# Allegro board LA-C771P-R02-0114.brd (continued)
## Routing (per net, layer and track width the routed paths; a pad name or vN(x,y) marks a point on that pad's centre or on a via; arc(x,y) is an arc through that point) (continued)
VCOUT0_MAIN_PWR_ON: length 174.8
  TOP w0.203: UB1.104 78.03,16.57 78.02,16.57
  TOP w0.254: v3(75.8,18.55) 75.8,18.35 77.58,16.57 78.02,16.57 ; v3(103.84,19.97) 103.84,13.04 v3(104.6,12.28)
  IN2 w0.254: v3(104.6,12.28) 105.11,11.77 109.16,11.77 109.87,11.06 124.15,11.06 128.31,6.89 179.33,6.89 203.43,31 203.43,41.97 202.11,43.29 196.04,43.29 195.77,43.56 v3(195.14,43.56) ; v3(75.8,18.55) 75.98,18.72 77.08,18.72 78.35,20 85.69,20 86,20.3 86.78,20.3 88.43,21.95 90.05,21.95 90.1,21.91 90.1,21.9 90.38,21.61 90.39,21.61 90.74,21.26 97.77,21.26 99.05,19.98 103.83,19.98 v3(103.84,19.97)
  BOTTOM w0.254: PR307.1 v3(195.14,43.56)
VCOUT1_PROCHOT#: length 197.1
  TOP w0.203: v3(119.21,8.37) 119.21,18.32 117.79,19.74 v3(117.79,19.73) ; v3(86.57,18.8) 86.57,18.47 84.94,16.84 84.94,16.54 84.79,16.39 84.05,16.39 PR111.1 ; RB24.1 82.46,16.08 81.92,16.62 v2(81.47,16.62) 81.21,16.62 80.76,16.17 UB1.103
  TOP w0.254: RB24.1 82.91,15.75 83.42,15.75 PR111.1
  IN2 w0.203: v3(207.58,68.06) 207.58,67.66 209.43,65.8 209.43,31 182.56,4.12 127.41,4.12 123.17,8.37 v3(119.21,8.37) ; v3(86.57,18.8) 86.93,18.8 87.93,19.81 95.32,19.81 95.76,19.37 103.14,19.37 103.29,19.22 107.03,19.22 107.27,19.22 107.79,19.74 117.79,19.74 v3(117.79,19.73)
  BOTTOM w0.203: v3(207.58,68.06) 206.03,69.6 PR224.1
VGA_CLKREQ#: length 9.1
  TOP w0.102: RPC3.3 124.35,93.18 v2(122.79,91.63) 120.85,89.68 120.28,89.68 v3(119.74,89.14)
  BOTTOM w0.102: UC4.BG3 120.25,89.14 v3(119.74,89.14)
VGA_V1P35_S3_F1:
  vias: v2(123.55,93.48)
VGATE: length 163.8
  TOP w0.203: v3(70.11,29.89) 70.13,29.87 UB1.21
  TOP w0.254: v3(102.93,31.15) 102.87,31.09 102.87,18.96 v3(102.95,18.88)
  IN2 w0.203: v3(102.95,18.88) 102.96,18.87 107.86,18.87 108.22,19.24 154.13,19.24 164,29.1 164,49.32 161.59,51.72 161.59,56.08 157.92,59.75 153.55,59.75 152.64,58.84 151.52,58.84 150.91,59.44 150.91,62.96 151.02,63.07 152.1,63.07 v3(152.14,63.1)
  IN2 w0.254: v3(102.93,31.15) 102.01,30.23 99.85,30.23 98.78,31.3 91.93,31.3 90.4,29.77 88.57,29.77 87.34,28.55 76.27,28.55 75.55,27.82 72.18,27.82 v3(70.11,29.89)
  BOTTOM w0.254: PU602.15 153.81,63.07 152.16,63.07 v3(152.14,63.1) 151.78,63.46 PR729.1
VGFX_VSNS: length 97.6
  TOP w0.254: v3(119.43,91.97) 118.79,91.33 118.22,91.33 v1(117.2,90.32) 116.9,90.01 116.9,86.54 117.22,86.22 v3(117.44,86.22) 117.63,86.03 117.63,84.26 118.07,83.82 118.73,83.82 119.08,83.47 119.08,82.01 119.43,81.67 RC71.2
  IN1 w0.254: v3(164.24,56.65) 166.59,59 166.59,78.61 165.5,79.7 165.5,80.73 161.24,85 152.72,85 152.18,85.54 150.16,85.54 149.35,84.73 147.56,84.73 146.74,85.54 133.88,85.54 129.7,89.72 129.17,89.72 126.71,92.18 119.64,92.18 v3(119.43,91.97)
  BOTTOM w0.254: UC4.BB8 117.61,86.22 v3(117.44,86.22) ; v3(164.24,56.65) 164.24,58.17 163.63,58.78 162.26,58.78 PC705.1 162,59.01 PR703.2 161.14,59.01 161.13,59 PR701.2
VL: length 76.3
  TOP w0.508: 22.51,7.58 R13.2 ; 22.51,7.58 22.99,8.06 31.96,8.06 v3(32.88,7.14) ; 22.51,7.58 22.16,7.93 16.7,7.93 R6.2
  IN1 w0.508: v3(45.27,51.16) 44.46,50.35 40.63,50.35 38.82,48.54 38.82,46.85 35.97,44 35.97,33.46 38.16,31.28 38.16,27.96 40.7,25.42 v3(40.7,14.54)
  IN2 w0.508: v3(32.88,7.14) 34.12,7.14 40.7,13.72 v3(40.7,14.54)
VMB:
  vias: v2(208.77,84.72)
VMB2:
  vias: v2(205.7,92.01) v2(207.54,92.62) v2(207.57,90.51)
VR_HOT#: length 123.6
  TOP w0.102: v3(85.99,18.78) v2(85.18,17.97) 84.43,17.22 RB26.1
  TOP w0.203: PR724.1 154.11,58.18 154.77,58.83 v3(154.92,58.83)
  IN2 w0.127: v3(154.92,58.83) 155.08,58.83 155.7,59.44 157.78,59.44 161.3,55.92 161.3,51.13 163.46,48.98 163.46,29.59 154.01,20.15 107.78,20.15 107.15,19.52 103.41,19.52 103.26,19.66 96.15,19.66 95.71,20.1 87.74,20.1 87.11,19.47 86.49,19.47 85.99,18.96 v3(85.99,18.78)
  BOTTOM w0.203: PU602.6 155.25,59.16 v3(154.92,58.83) 155,58.75 PC744.1
VR_ON: length 147.1
  TOP w0.203: UB1.108 78.6,18.17 78.18,18.59
  TOP w0.254: 78.18,18.59 76.91,19.86 v3(76.49,19.86)
  BOTTOM w0.203: v3(76.49,19.86) 77.62,19.86 v2(78.11,20.35) 78.89,21.14 84.24,21.14 85.15,20.23 88.6,20.23 88.86,19.97 102.09,19.97 102.57,19.49 113.34,19.49 116.13,16.7 120.88,16.7 127.87,9.71 161.66,9.71 166.15,14.2 166.15,44.01 158.08,52.08 PR717.1
VR_SVID_ALERT#: length 95.8
  TOP w0.102: v3(156.26,58.78) 156.26,58.82 156.81,59.37 v2(156.85,59.37)
  IN2 w0.127: v3(90.2,79.26) 90.2,79.99 91.37,81.16 95.69,81.16 96.07,80.78 97.49,80.78 100.11,78.16 100.29,78.16 100.49,77.96 104.93,77.96 105.26,77.63 105.26,76.18 105.57,75.87 105.57,75.21 105.29,74.94 105.29,74.55 105.47,74.38 105.95,74.38 106.64,73.69 106.64,72.84 106.98,72.5 108.17,72.5 108.3,72.36 108.3,72.36 109.37,71.3 112.44,71.3 113.28,70.45 116.33,70.45 118.34,68.43 118.34,67.67 119.49,66.53 119.82,66.53 121.01,65.33 121.01,64.42 121.66,63.77 121.66,62.7 134.75,49.62 153.17,49.62 155.53,51.97 155.53,57.66 156.26,58.4 v3(156.26,58.78)
  BOTTOM w0.102: RC39.2 89.74,78.57 RC40.2 89.8,78.62 90.2,79.03 v3(90.2,79.26) ; v3(156.26,58.78) 156.26,58.82 156.05,59.03 PU602.4
VR_SVID_ALERT#_SOC: length 10
  TOP w0.102: v3(95.68,78.92) v2(95.68,78.27)
  IN2 w0.102: 95.15,79.33 95.28,79.33 v3(95.68,78.92)
  IN2 w0.127: v3(90.91,79.56) 90.91,79.13 91.14,78.9 92.93,78.9 93.36,79.33 95.15,79.33
  BOTTOM w0.102: UC4.B24 98.22,78.91 97.58,78.91 97.42,78.75 95.86,78.75 v3(95.68,78.92) ; v3(90.91,79.56) 90.91,78.83 RC40.1
VR_SVID_CLK: length 99.4
  TOP w0.102: PR726.1 157.35,56.66 v3(157.35,56.54)
  IN2 w0.127: v3(157.35,56.54) 157.35,52.14 153.66,48.45 134.26,48.45 119.65,63.06 119.65,64.44 118.7,65.4 118.09,65.4 117.43,66.06 117.43,66.63 114.84,69.22 113.54,69.22 112.27,70.49 109.53,70.49 108.06,71.96 106.86,71.96 106.18,72.65 106.18,73.49 105.8,73.87 104.81,73.87 104.35,74.32 104.35,76.76 103.77,77.35 101.2,77.35 100.79,76.94 99.83,76.94 99.4,77.37 99.4,77.86 97.42,79.84 93.15,79.84 92.72,79.41 91.59,79.41 91.52,79.47 v3(91.52,79.51)
  BOTTOM w0.102: PR726.1 157.35,56.66 v3(157.35,56.54) ; v3(91.52,79.51) 91.52,78.13 v1(91.89,77.76) 91.95,77.69 95.3,77.69 95.64,78.03 97.9,78.03 98.15,78.29 98.44,78.29 UC4.C25
VR_SVID_CLK_R: length 5.4
  TOP w0.102: v2(159.52,57.13) 158.73,57.13 v3(157.08,58.78)
  BOTTOM w0.102: PR720.2 157.08,58.44 v3(157.08,58.78) 156.45,59.41 PU602.3
VR_SVID_DATA: length 89.8
  TOP w0.102: PR725.1 156.11,57 v3(156.11,56.5)
  IN2 w0.127: v3(156.11,56.5) 156.11,51.73 153.41,49.03 134.5,49.03 120.24,63.3 120.24,64.69 118.94,65.98 118.36,65.98 118.02,66.33 118.02,66.88 117,67.89 117,68.86 115.96,69.91 113.35,69.91 112.33,70.92 109.42,70.92 108.08,72.27 106.88,72.27 106.41,72.74 106.41,73.59 105.85,74.15 105.29,74.15 104.98,74.45 104.98,74.96 105.29,75.27 105.29,75.7 104.91,76.08 104.91,76.69 103.94,77.65 100.39,77.65 100.18,77.86 99.88,77.86 97.31,80.42 92.56,80.42 v3(92.13,79.99)
  BOTTOM w0.102: v3(156.11,56.5) 156.11,57 PR725.1 ; v3(92.13,79.99) 92.36,79.76 RC41.2
VR_SVID_DATA_R: length 3.5
  TOP w0.102: v2(154.74,59.88) 155.65,58.97 v3(155.65,58.76)
  BOTTOM w0.102: PU602.5 v3(155.65,58.76) 155.89,58.52 PR721.2
VR_SVID_DATA_SOC: length 5
  BOTTOM w0.102: UC4.A25 97.7,78.29 95.3,78.29 95.07,78.06 v2(94.69,78.06) 93.91,78.06 RC41.1
VSUM+: length 8.1
  TOP w0.203: PC758.1 PC759.1 PR739.1 151.45,60.41 151.39,60.35 PR735.2 ; PR735.2 151.39,59.09 151.46,59.02 PR734.1 v2(151.46,57.77) ; PR735.2 v3(152.28,59.72)
  BOTTOM w0.203: v3(152.28,59.72) 152.28,59.72 152.65,60.08 152.88,60.08 153.12,60.31 153.12,60.82 153.36,61.07 PU602.10
VSUM-: length 22.8
  TOP w0.203: PC761.2 150.12,63.44 150.13,63.46 PR738.2 PC758.2 PC759.2 ; PR739.2 v2(148.32,60.79) 146.92,60.79 v3(146.85,60.87)
  TOP w0.254: PR739.2 PC759.2
  IN2 w0.203: v3(149.56,67.06) 148.37,67.06 147,65.69 147,61.02 v3(146.85,60.87)
  BOTTOM w0.203: v3(149.56,67.06) 149.97,67.47 PH701.2 149.97,71.58 149.29,72.26 PL703.3
VSUMG+: length 7.2
  TOP w0.254: v3(159.16,59.47) 159.55,59.47 159.81,59.73 PR714.2 ; PC727.2 PC726.2 PR711.2 160.23,60.31 160.28,60.25 PR714.2 ; PR714.2 160.28,59.14 160.22,59.07 PR710.2
  BOTTOM w0.254: v3(159.16,59.47) 158.96,59.47 158.58,59.85 158.58,60.36 158.27,60.67 PU602.32
VSUMG-: length 52.8
  TOP w0.254: PR704.2 162,63.46 PR706.1 PC727.1 PC726.1 PR711.1 164.27,60.79 v3(164.37,60.69)
  IN2 w0.203: v3(164.37,60.69) 166.31,62.63 166.31,78.53 165.27,79.57 165.27,81.78 162.22,84.83 153.03,84.83 152.45,85.42 151.15,85.42 v3(150.67,84.93)
  BOTTOM w0.203: v3(150.67,84.93) 150.08,84.93 PH702.1 149.82,80.96 149.34,80.47 PL702.3
VTTREF_DDR: length 5.1
  BOTTOM w0.102: 154.24,35.88 153.98,36.15 153.98,37.09 v2(154.34,37.45)
  BOTTOM w0.203: PC415.1 154.12,34.87 154.12,34.04 154.07,34 PU303.4
  BOTTOM w0.254: PC415.1 154.24,35.88
WAKE#_R: length 5.7
  BOTTOM w0.102: v1(177.03,89.34) RM2.2 174.37,89.34 RM3.2 174.33,89.62 172.95,91 JWLAN1.1
WL_RST#: length 4.4
  TOP w0.102: JWLAN1.22 161.35,93 162.34,92.01 RM6.1 v1(161.25,91.32)
WLAN_BT_OFF#: length 32.7
  TOP w0.102: v3(150.59,90.05) 150.08,89.54 149.64,89.54 v1(149.36,89.83) 149.36,89.83 148.83,90.36 148.83,91.27 RM21.1
  IN1 w0.127: v3(172.17,87.13) 171.95,87.13 170.43,88.65 169.13,88.65 168.64,89.15 166.85,89.15 166.05,89.95 161.74,89.95 161.45,89.66 156.57,89.66 156.03,90.2 154.34,90.2 153.76,89.63 150.82,89.63 150.59,89.86 v3(150.59,90.05)
  BOTTOM w0.102: v3(172.17,87.13) 172.23,87.19 QM1.3 172.23,88.29 RM18.1 171.1,89.42 171.1,90.46 171.35,90.71 JWLAN1.5
WLAN_CLKREQ#: length 75.5
  TOP w0.102: v3(118.52,89.18) 119.56,90.23 120.71,90.23 123.85,93.37 v1(123.85,93.9) RPC3.2
  IN1 w0.127: v3(169.83,87.72) 169.06,86.94 167.62,86.94 165.63,88.93 162.17,88.93 161.88,88.64 156.69,88.64 156.27,88.22 154.22,88.22 153.82,88.62 149.42,88.62 138.17,99.87 126.63,99.87 125.13,98.37 123.69,98.37 v3(122.85,97.53)
  IN2 w0.102: v3(118.52,89.18) 118.52,90.1 118.88,90.46 118.88,90.48 119.15,90.75
  IN2 w0.127: 119.15,90.75 119.82,91.42 120.22,91.42 123.06,94.26 123.06,94.83 122.85,95.03 v3(122.85,97.53)
  BOTTOM w0.102: RM4.1 169.82,87.78 169.82,87.73 v3(169.83,87.72) ; UC4.BE3 118.61,89.09 v3(118.52,89.18)
WLAN_CLKREQ#_R: length 3.6
  BOTTOM w0.102: RM4.2 v1(170.11,89.37) 170.55,89.81 JWLAN1.7
XDP_H_PRDY#: length 13
  BOTTOM w0.102: UC4.D18 99.51,81.93 99.04,82.4 98.75,82.56 98.63,82.67 98.63,82.82 98.2,83.24 98.2,83.37 97.49,84.08 96.65,84.08 96.27,84.46 95.15,84.46 v1(93.81,85.81) 93.64,85.98 89.07,85.98 RC38.2
XDP_H_PREQ_BUF#: length 4.3
  TOP w0.102: v2(96.8,82.17) 97.78,82.17 RC45.2 98.54,81.62 98.84,81.92 99.6,81.92 v3(99.93,82.25)
  BOTTOM w0.102: UC4.F16 100.19,82.51 v3(99.93,82.25)
XDP_H_TCK: length 14.4
  TOP w0.102: RPC6.7 88.81,83.33 90.07,84.59 91.88,84.59 v2(92.24,84.95) 92.38,85.09 v3(93.53,85.09)
  IN2 w0.102: 95.15,84.87 95.68,84.87 96.34,84.21 97.75,84.21 98.05,83.91 99.32,83.91 v3(99.68,84.27)
  IN2 w0.127: 95.15,84.87 94.59,84.87 94.33,85.13 93.57,85.13 v3(93.53,85.09)
  BOTTOM w0.102: UC4.D14 99.51,84.1 v3(99.68,84.27)
XDP_H_TDI: length 15.6
  TOP w0.102: RPC6.5 v2(88.65,82.33) 89.33,82.32 90.33,83.32 v3(90.71,83.32)
  IN2 w0.102: 95.15,84.26 95.72,84.26 96.96,83.02 99.61,83.02 v3(99.81,83.21)
  IN2 w0.127: v3(90.71,83.32) 91.1,83.71 93.13,83.71 93.68,84.26 95.15,84.26
  BOTTOM w0.102: UC4.F12 100.07,84.65 100.07,84.12 99.88,83.92 99.88,83.28 v3(99.81,83.21)
XDP_H_TDO: length 1.9
  TOP w0.102: RC46.2 100.79,82.22 v3(100.71,82.3)
  BOTTOM w0.102: v3(100.71,82.3) 100.9,82.49 UC4.G16
XDP_H_TMS: length 15.3
  TOP w0.102: RPC6.6 89,82.83 89.97,83.8 v2(90.38,83.8) 90.83,83.8 v3(91.35,83.28)
  IN2 w0.102: v3(100.41,83.26) 99.95,82.81 96.88,82.81 95.73,83.96 95.29,83.96
  IN2 w0.127: 95.29,83.96 93.74,83.96 93.06,83.28 v3(91.35,83.28)
  BOTTOM w0.102: v3(100.41,83.26) 100.19,83.48 UC4.F14
XDP_H_TRST#: length 16.4
  TOP w0.102: RPC6.8 88.5,83.83 89.57,84.9 91.32,84.9 91.96,85.53 94.06,85.53 94.24,85.35 v2(94.24,85.2) 94.24,84.94 v3(93.99,84.69)
  IN2 w0.102: 95.15,84.57 95.7,84.57 96.3,83.96 97.67,83.96 97.92,83.71 100.06,83.71 v3(100.52,84.18)
  IN2 w0.127: v3(93.99,84.69) 94.11,84.57 95.15,84.57
  BOTTOM w0.102: v3(100.52,84.18) 100.9,84.55 UC4.G12
XDP_OBSDATA_A0: length 2.5
  TOP w0.102: T10.1 101.88,80.07 v3(102.53,79.42)
  BOTTOM w0.102: UC4.N24 103.22,79.42 v3(102.53,79.42)
XDP_OBSDATA_A1: length 2.1
  TOP w0.102: T11.1 102.42,80.68 v3(102.11,80.37)
  BOTTOM w0.102: v3(102.11,80.37) 102.54,80.37 UC4.M20
XDP_OBSDATA_A2: length 1.7
  TOP w0.102: T12.1 101.34,81.94 v3(101.34,82.3)
  BOTTOM w0.102: v3(101.34,82.3) 101.61,82.04 UC4.J18
XDP_OBSDATA_A3: length 1.2
  TOP w0.102: v3(102.6,82.22) 102.6,82.35 T13.1
  BOTTOM w0.102: v3(102.6,82.22) 103.01,81.81 UC4.M18
XDP_RSTBTN#: length 5.9
  BOTTOM w0.102: UC4.BG9 120.92,86.15 121.32,86.55 122.34,86.55 122.88,87.09 122.88,87.55 123.33,88 T7.1 124.75,88.12 CC15.1
XTAL_25M_IN: length 13.5
  IN2 w0.127: v3(112.5,90.86) 112.2,90.56 112.2,86.12 111.5,85.41 v3(110.57,85.41)
  BOTTOM w0.102: UC4.AH12 110.75,85.41 v3(110.57,85.41) ; v3(112.5,90.86) 112.5,91.09 112.02,91.58 112.02,92.97 RC24.1 111.94,93.07 111.28,93.73 111.03,93.73 110.59,94.17 CC12.1 110.59,95.24 YC1.1
XTAL_25M_OUT: length 14.9
  IN2 w0.127: v3(110.61,86.01) 111.56,86.01 111.97,86.42 111.97,90.87 111.36,91.48 v3(111.36,92.34)
  BOTTOM w0.102: v3(111.36,92.34) 111.03,92.67 RC24.2 110.6,93.05 109.53,94.12 CC13.1 109.85,94.73 109.85,96.44 YC1.3 ; UC4.AH10 110.84,85.78 v3(110.61,86.01)
XTLI: length 8.4
  BOTTOM w0.102: YL1.3 36.81,60.06 36.81,62.16 36.35,62.62 36.35,63.5 35.57,64.29 CL16.2 35.57,65.77 35.47,65.87 UL1.29
XTLO: length 6.1
  BOTTOM w0.102: UL1.28 35.87,65.95 35.87,65.95 35.87,65.69 v2(36.14,65.42) 37.01,64.55 CL13.2 37.01,64.29 37.5,63.81 37.5,61.55 YL1.1
N10380:
  vias: v2(37.77,89.47)
N16597291: length 1.1
  BOTTOM w0.102: PR304.2 v2(185.83,40.51)
N16598283: length 1.2
  BOTTOM w0.102: PC318.1 v2(50.53,49.87)
N16598457: length 1.9
  BOTTOM w0.102: v2(191.58,43.85) PC302.2 191.58,42.87
  BOTTOM w0.254: PR302.1 191.58,42.87 191.58,42.87
N16598563: length 1
  BOTTOM w0.254: PR309.1 PC317.2
N16600766: length 2.7
  TOP w0.381: v2(154.62,28.94) 154.13,28.46 v3(154.13,28.43)
  TOP w0.508: v3(154.13,28.43) 154.13,28.07 PC408.2 155.46,27.71 PR405.2
N16601416: length 2.9
  TOP w0.508: v2(151.47,27.25) PC417.1 150.18,27.82 PR403.2
N16602606:
  vias: v2(64.82,59.25)
N16602704:
  vias: v2(65.67,62.39)
N16603012: length 1.7
  TOP w0.254: PU501.2 60.94,59.18 v3(60.7,58.95) 60.12,58.37 PR502.2
N16605295: length 1.7
  TOP w0.102: PC602.1 71.71,79.79 v2(72.25,79.79)
N16605323: length 4.8
  TOP w0.102: v2(63.68,73) 63.68,72.77 64.3,72.15 64.6,72.15 PR603.2
  TOP w0.254: PU601.2 PR605.1 PC604.2 PR603.2
N16605357: length 2.3
  TOP w0.254: PU601.7 66.38,79.5 66.79,79.9 67.15,79.9 67.46,80.21 PR602.2
N16605441: length 5.6
  TOP w0.254: PR604.1 PC603.1 PR601.2 64.79,80.51 63.9,80.51 63.65,80.26 v2(63.65,79.97) 63.65,79.78 63.83,79.6 64.8,79.6 65.11,79.29 PU601.8
N16615810: length 3.3
  BOTTOM w0.203: PU602.8 154.45,59.97 153.83,59.34 152.92,59.34 v2(152.66,59.09) 152.33,58.76 PR722.2
N16616404: length 1.2
  BOTTOM w0.102: PR709.1 v2(162.52,64.53)
N16616872: length 1.4
  BOTTOM w0.102: PR730.1 151.25,66.72 v2(151.57,67.04)
N16617014: length 2.2
  TOP w0.102: v2(163.3,64.35) 163.3,64.36 PR704.1
  TOP w0.203: PR704.1 162,64.35 PC716.1
N16617018: length 5.1
  TOP w0.254: PC716.2 PR706.2 160,63.46 158.99,62.45 v2(158.99,61.78) 158.99,61.17 v3(158.78,60.96)
  BOTTOM w0.254: v3(158.78,60.96) 158.67,61.07 PU602.31
N16617032: length 1.9
  TOP w0.102: PC761.1 149.61,64.41 v2(149.61,65.31)
  TOP w0.203: PC761.1 149.67,64.35 PR737.2
N16617036: length 5.4
  TOP w0.203: PR737.1 PR738.1 151.68,63.69 152.52,63.69 152.83,63.37 v2(152.83,62.77) 152.83,61.52 v3(152.97,61.38)
  BOTTOM w0.203: PU602.11 153.05,61.47 v3(152.97,61.38)
N16617104: length 4.2
  BOTTOM w0.203: PC713.1 160.23,60.82 PR702.1 PR707.1 159.7,62.57 159.4,62.27 PU602.28
N16617138: length 3.1
  TOP w0.102: v3(157.83,58.77) 158.25,58.35 v2(158.25,58.33)
  BOTTOM w0.203: PR717.2 158.08,58.52 v3(157.83,58.77) 157.31,59.29 157.16,59.29 156.85,59.6 PU602.2
N16617166: length 6.4
  TOP w0.102: PR123.2 156.47,55.3 v1(157.06,54.72)
  TOP w0.203: PR123.2 155.86,55.76 155.33,56.3 PR122.2 155.02,56.5 PC750.1 PR724.2 155.87,58.12 PR725.2 PR726.2
N16617198: length 8.7
  BOTTOM w0.102: v2(163.38,59.62) 163.11,59.89 PR705.1
  BOTTOM w0.203: PC713.2 159.67,60.46 159.67,61.43 159.23,61.87 PU602.29 ; PC713.2 160.24,59.03 PR703.1 160.23,58.15 PC714.1 ; PC713.2 PC719.2 PR705.1
N16617206: length 4.2
  BOTTOM w0.203: PC757.2 151.44,61.67 PC760.2 151.45,61.68 151.45,62.56 PR732.2 152.38,62.57 v2(152.39,62.58) 152.48,62.67 PU602.14
N16617222: length 12.1
  BOTTOM w0.102: v2(146.59,62.29) 147.58,61.3 149.03,61.3 149.18,61.15 149.18,60.37 PR733.2
  BOTTOM w0.203: PC757.1 151.98,60.43 151.98,61.54 152.7,62.27 PU602.13 ; PC757.1 PR741.1 PR733.2 ; PC757.1 151.45,59.88 PR740.2 151.44,59 PR736.2
N16617226: length 0.9
  BOTTOM w0.203: PR702.2 161.14,61.29 161.13,61.27 PC719.1
N16617230: length 5
  BOTTOM w0.102: PC738.1 154.03,66.45 v2(153.33,67.14)
  BOTTOM w0.254: PC738.1 154.51,66.45 155.41,66.45 PR719.2 155.41,66.37 155.94,65.84 155.94,65.28 156.05,65.17 PU602.21
N16617308: length 2.7
  BOTTOM w0.254: PU602.27 159.18,62.67 159.97,63.46 PR712.2
N16617390: length 0.9
  BOTTOM w0.203: PC760.1 150.55,61.67 PR741.2
N16617462: length 3.4
  BOTTOM w0.102: v2(148.5,57.75) 149.36,56.89 150.22,56.89 PC756.2
  BOTTOM w0.254: PR736.1 151.43,57.23 150.55,57.23 PC756.2
N16617530: length 47.4
  TOP w0.203: v3(163.1,58.02) 162.44,58.68 PR710.1
  IN2 w0.203: v3(148.91,85.35) 149.03,85.48 150.73,85.48 151.05,85.8 152.58,85.8 153.21,85.16 162.35,85.16 165.73,81.79 165.73,79.85 166.85,78.74 166.85,61.77 v3(163.1,58.02)
  BOTTOM w0.203: PH702.2 v3(148.91,85.35)
N16617586: length 2.4
  BOTTOM w0.102: 149.66,61.67 149.19,62.14 v2(148.37,62.14)
  BOTTOM w0.203: 149.66,61.67 PC752.2 PR733.1
N16617598: length 2.1
  BOTTOM w0.102: PR701.1 161.68,56.67 v2(161.68,56.19)
  BOTTOM w0.203: PC714.2 PR701.1
N16617710: length 3.3
  BOTTOM w0.254: PR718.1 156.31,66.45 ; 156.31,66.45 157.19,66.45 PC733.2 ; 156.31,66.45 156.31,66.18 156.45,66.03 v2(156.45,65.41) PU602.22
N16617722: length 13.7
  TOP w0.203: PR734.2 149.96,58.67 v2(149.58,58.3) 148.66,58.3 v3(146.87,60.08)
  IN2 w0.203: v3(149.03,66.56) 148.85,66.73 148.51,66.73 147.33,65.56 147.33,60.54 v3(146.87,60.08)
  BOTTOM w0.203: PH701.1 149.05,66.58 v3(149.03,66.56)
N16617766: length 1.8
  BOTTOM w0.102: PC724.1 v2(163,61.67)
  BOTTOM w0.254: PR705.2 PC724.1
N16618186: length 0.8
  TOP w0.102: 150.27,81.01 150.38,80.91 v2(151.01,80.91)
N16618510: length 45.6
  TOP w0.203: v3(162.8,59.32) 162.59,59.52 161.89,59.52 PR714.1
  IN2 w0.203: v3(162.8,59.32) 162.8,60.71 164.22,62.14 164.22,81.47 161.25,84.43 152.8,84.43 152.16,85.07 151.52,85.07 v3(151.29,84.84)
  BOTTOM w0.203: PL702.2 150.76,80.47 150.46,80.77 150.46,84.02 v3(151.29,84.84)
N16618534: length 17.1
  TOP w0.203: PR735.1 148.58,59.72 v3(148.55,59.75)
  IN2 w0.203: v3(148.55,59.75) 148.24,60.05 148.24,64.5 v3(150.48,66.73)
  BOTTOM w0.203: v3(150.48,66.73) 150.48,71.44 151.29,72.26 PL703.2
N17087503: length 2.5
  TOP w0.305: UR1.8 v2(44.2,14.23) 43.31,13.33 RR1.2
N17458820: length 5.6
  TOP w0.102: LED3.1 24.29,2.74 v2(24.29,3.54) 24.29,4.07 23.55,4.81 R12.2 23.56,5.44 R15.2
N17500377: length 1.9
  TOP w0.203: UQ1.12 v3(186.7,25) 185.55,25 CQ2.2
N17500401: length 2.1
  TOP w0.203: CQ6.2 185.7,26.15 v3(186.17,26.15) 186.53,25.8 UQ1.10
N17500568: length 2.3
  TOP w0.203: CQ10.2 55.28,68.18 v2(54.41,68.18) 53.98,68.18 53.68,67.88 UQ2.12
N17500584: length 2.2
  TOP w0.203: UQ2.10 54.12,67.08 v3(54.19,67.01) 55.18,67.01 CQ14.2
N18372963: length 2.6
  BOTTOM w0.229: UL1.31 34.67,66.14 34.37,65.85 v2(34.37,65.49)
  BOTTOM w0.254: v2(34.37,65.49) 34.37,64.3 RL6.2
N18373572: length 4.4
  BOTTOM w0.102: UL1.25 37.07,66.15 37.55,65.67 38.21,65.67 38.67,65.21 39.15,65.21 39.73,64.63 TPL1.1
N18373578: length 2.7
  BOTTOM w0.102: TPL2.1 37.37,65.06 36.27,66.16 UL1.27
N18442348: length 3.3
  TOP w0.203: UB1.118 81.11,22.17 v2(81.5,22.56)
  TOP w0.254: v2(81.5,22.56) 82.13,23.19 82.13,23.2 RB25.2
N18492193:
  vias: v2(118.25,56.88)
N18492196:
  vias: v2(115.13,56.84)
N18535411: length 1.7
  TOP w0.102: v2(19.46,71) 18.27,71 RL8.2
N18535413: length 4
  BOTTOM w0.508: v3(19.78,64.4) 19.12,63.74 TL1.11 ; v3(19.73,68.42) 18.85,67.55 TL1.14
  vias: v1(19.96,69)
N18977277: length 4.1
  BOTTOM w0.102: v2(50.68,81.67) 51.7,82.69 CX13.1 51.75,82.71 RX11.2 51.75,84.84 QX2.2
N19132918: length 3.8
  BOTTOM w0.102: UC5.4 54.47,78.85 54.29,79.02 54.29,79.74 54.02,80.01 v2(53.49,80.01) 53.49,78.83 RC8.1
N19342204: length 4
  BOTTOM w0.102: RC12.1 60.89,77.15 59.95,77.15 v2(59.57,77.53) 59.57,78.31 UC6.4
N19670814: length 5.9
  BOTTOM w0.102: PR109.1 PR105.1 PR107.1 199.99,91.15 199.08,91.15 v2(198.97,91.27) 198.85,91.38 JBATT1.5
N19670901: length 2.9
  BOTTOM w0.102: v1(148.94,15.11) PR116.1
  BOTTOM w0.508: PR116.1 147.79,16.52 PD100.3
N19732471: length 5.1
  TOP w0.102: v2(123.81,89.44) v3(123.81,88.68)
  BOTTOM w0.254: RC74.2 124.57,89.79 124.04,89.26 124.04,88.91 v3(123.81,88.68) 123.02,88.68 122.22,87.88 121.6,87.88 UC4.BJ6
N19773650: length 5.3
  TOP w0.102: RW7.1 93.25,18.17 RW4.2 93.22,17.14 RW3.2 93.21,17.02 RW6.1 92.29,15.23 92.29,15.23 v2(92.29,14.51)
N19773695: length 6.6
  TOP w0.102: UW2.6 96.74,15.59 96.45,15.3 96.45,14.84 96.15,14.54 94.42,14.54 v2(94.14,14.82) 94.14,15.25 94.52,15.63 RW9.1 93.24,16.13 RW6.2
N19773710: length 4.5
  TOP w0.102: UW2.5 96.61,16.24 95.69,17.15 RW8.2 RW9.2 95.43,15.4 v2(95.9,14.93)
N19796007: length 14.2
  BOTTOM w0.102: v2(29.5,61.51) 29.5,61.03 CL15.1
  BOTTOM w0.254: CL15.1 28.65,60.18 27.87,60.18 27.86,60.18 27.8,60.18 27.79,60.18 26.02,60.18 25.59,60.61 25.59,63.41 25.92,63.74 ; 25.92,63.74 TL1.6 ; 25.92,63.74 25.56,64.09 25.56,67.29 25.81,67.55 TL1.3
N19801797: length 5.3
  BOTTOM w0.102: US1.3 16.48,38.35 16.21,38.08 v2(15.93,38.08) 15.64,38.08 15.27,38.45 RS2.1
N19854769: length 5.5
  TOP w0.102: JWLAN1.20 162.15,93.16 162.59,92.72 163.48,92.72 RM5.1 v1(165.86,91.32)
N19857635: length 6.1
  TOP w0.102: v1(153.56,88.06) 152.09,89.53 151.72,89.53 151.25,90 v3(151.25,90.05) 151.06,90.24 RM11.2
  BOTTOM w0.102: v3(151.25,90.05) 151.25,90.03 150.55,90.73 JWLAN1.49
N19992411: length 5
  TOP w0.254: v3(129.22,48.82) 127.82,47.42 RD5.2
  BOTTOM w0.254: v3(129.22,48.82) 128.33,47.94 JDIMM1.197
N19992423: length 5
  TOP w0.508: RD6.2 129.63,45 130.16,44.48 v3(130.52,44.48)
  BOTTOM w0.356: v3(130.52,44.48) 130.16,44.48 129.53,45.11 JDIMM1.201
N20191994: length 3.8
  TOP w0.102: v3(149.98,90.04) 149.98,90.12 RM21.2 RM12.2
  BOTTOM w0.102: v3(149.98,90.04) 149.98,90.03 149.75,90.26 JWLAN1.51
N20264849: length 4.6
  TOP w0.254: RS11.1 190.28,61.07 190.74,61.53 v2(191.09,61.53) 191.68,61.53 193.14,60.07 US2.13
N20529644: length 6.4
  TOP w0.102: v1(186.05,56.19) 186.04,56.19 186.8,55.43 186.8,55.31 RS20.1 187.1,54.62 188.37,53.35 188.37,52.46 187.99,52.08 187.35,52.08 US3.3
N20531465: length 4.2
  BOTTOM w0.102: QM1.5 171.73,85.6 RM20.1 ; RM20.1 170.98,85.35 170.98,85.89 171.23,86.14 QM1.6 ; RM20.1 v2(171.23,84.11)
N20897061: length 3.9
  TOP w0.102: R7.1 20.83,5.47 20.61,5.24 v2(20.61,4.4) 20.61,4.17 20.84,3.95 21.37,3.95 21.65,3.67 LED2.2
N20897066: length 2.6
  TOP w0.102: R13.1 22.51,4.56 v2(22.71,4.36) 23.15,3.91 LED3.2
N20897117: length 2.4
  TOP w0.102: R14.1 30.4,5.46 v2(30.4,4.35) LED4.2
N20897124: length 3.3
  TOP w0.102: LED1.2 14.4,3.1 15.01,3.1 15.5,3.59 v2(15.5,4.12) 15.5,5.11 R6.1
N21018227: length 3.4
  TOP w0.102: JODD1.11 225.77,109.74 223.63,109.74 T22.1
N23009332: length 3.9
  TOP w0.102: UA1.47 28.26,26.28 28.48,26.5 28.48,27.64 v2(29.07,28.23) 29.32,28.48 RA12.2
N23009443: length 2
  TOP w0.102: RA11.2 28.15,33.5 CA10.1 v2(29.17,33.48)
N23009457: length 4.6
  BOTTOM w0.102: v2(21.24,31.53) 21.24,31.08 RA30.1 22.54,29.77 RA31.1 23.17,29.5 CA30.2 23.83,29.51 CA32.2
N23009590: length 2.9
  BOTTOM w0.102: RA30.2 20.1,30.36 19.9,30.16 v2(19.9,30.01) 19.9,29.73 20.15,29.47 CA31.1
N23009788: length 1.8
  TOP w0.203: UA1.28 23.77,20.95 23.63,20.81 23.63,20.15 CA20.1
N23009828: length 2.2
  TOP w0.203: UA1.19 20.88,24.28 v3(20.73,24.42)
  BOTTOM w0.254: v3(20.73,24.42) 20.15,24.42 CA21.1
N23009845: length 4.1
  TOP w0.203: CA15.2 29.55,20.61 29.03,20.61 28.23,21.42 v3(28.23,21.78) 28.38,21.93 28.38,22.14 28.24,22.28 UA1.37
N23009849: length 6.1
  TOP w0.102: v2(30.54,18.04) 30.54,18.7 CA15.1
  TOP w0.203: CA15.1 30.13,18.98 28.74,20.38 27.1,20.38 26.57,20.91 UA1.35
N24385312: length 3.3
  BOTTOM w0.203: PU1.10 203.67,71.38 v2(203.95,71.1) 204.24,70.81 PR224.2
N24385422: length 1.4
  BOTTOM w0.102: PR220.2 v2(194.72,69.38)
N24385504: length 12.9
  TOP w0.102: v2(43.44,85.76) 43.44,86.14 v3(43.67,86.37)
  IN1 w0.508: v3(43.67,86.37) 39.76,86.37 37.98,84.59 v3(37.85,84.59)
  BOTTOM w0.381: PR211.1 38.51,86.16 39.15,86.79 39.33,86.79 PQ200.3 40.11,88.58 PR201.2
  BOTTOM w0.508: v3(37.85,84.59) 37.98,84.72 PR211.1
N24385542:
  vias: v2(187.56,67.95) v3(184.95,68.46) v3(185.64,68.46) v3(186.34,68.46)
N24385544: length 2.7
  BOTTOM w0.203: PU1.21 199.18,67.69 PR225.1 PR222.1
N24385582: length 1.7
  BOTTOM w0.203: PR226.1 199.58,67.31 PU1.20
N24385584: length 2.6
  TOP w0.102: v2(200.72,68.21) 200.31,68.21 v3(200.06,67.95)
  BOTTOM w0.203: PR227.1 200.5,67.51 v3(200.06,67.95) 199.98,68.04 PU1.19
N24385612: length 1.8
  TOP w0.102: v2(197.75,73.64) 197.27,73.64 v3(196.91,73.28)
  TOP w0.508: PC211.2 196.06,73.28 v3(196.91,73.28)
N24385618: length 5
  TOP w0.102: v2(201.05,77.83) 201.05,77.47 v3(201.32,77.2)
  BOTTOM w0.102: v3(201.32,77.2) PR215.2
  BOTTOM w0.203: PR216.1 201.39,74.67 201.39,73.73 201.18,73.52 PU1.6
  BOTTOM w0.254: PR216.1 PC212.1 PR215.2
N24385720: length 0.8
  BOTTOM w0.508: PC201.1 v3(188.44,79.64)
  vias: v2(188.83,80.35)
N24386383: length 10.5
  TOP w0.102: v3(40.52,85.56) 40.55,85.53 v2(40.55,84.92)
  IN1 w0.508: v3(46.85,84.29) 42.96,84.29 41.69,85.56 v3(40.52,85.56)
  BOTTOM w0.508: v3(46.85,84.29) 47.02,84.29 PC202.2 47.45,85.28 46.74,85.28 46.29,85.73 PQ202.4
N24386409: length 5.9
  BOTTOM w0.508: PR214.1 195.93,75.95 v2(197.32,77.35) 197.84,77.86 199.55,77.86 200.19,78.49 PD1.1
N24386941: length 1.2
  TOP w0.102: v2(193.61,74.58) 193.61,73.44 PR217.2
N28204186:
  vias: v2(195.54,66.91)
N100842872: length 2
  TOP w0.102: RC53.2 CC26.2 v2(50.57,35.1)
N102723193: length 3.3
  TOP w0.102: T6.1 122.7,82.51 121.9,82.51 121.78,82.64 120.91,82.64 120.59,82.31 v3(120.21,82.31)
  BOTTOM w0.102: v3(120.21,82.31) 120.38,82.14 UC4.BG18
N102723222: length 2.8
  BOTTOM w0.102: UC4.BH18 121.19,81.93 123.12,81.93 T5.1
N102723231: length 3.1
  BOTTOM w0.102: UC4.BG21 120.83,80.26 121.13,80.26 121.27,80.12 121.3,80.08 121.77,79.61 122.03,79.61 122.84,78.81 T4.1
N103320637: length 5.4
  BOTTOM w0.102: T9.1 94.36,80.91 95.03,80.24 97.42,80.24 97.58,80.08 98.01,80.08 98.12,80.19 98.41,80.19 UC4.C21

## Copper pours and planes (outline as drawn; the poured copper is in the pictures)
3V_SN on BOTTOM (solid shape): 195.56,33.99 195.56,32.09 195.49,32.01 193.61,32.01 193.15,32.47 193.15,34.25 193.27,34.37 195.17,34.37
3V_VIN on BOTTOM (solid shape): 190.61,39.22 190.61,37.21 190.59,37.19 190.48,37.19 189.74,36.45 189.74,33.4 189.68,33.33 188.86,33.33 187.41,34.78 187.41,34.98 187.13,35.26 187.13,36.37 187.33,36.57 187.96,36.57 188.22,36.83 188.22,38.35 188.28,38.41 188.79,38.41 189.02,38.64 189.02,39.05 189.19,39.22 190.6,39.22
5V_SN on BOTTOM (solid shape): 41.03,44.09 41.03,42.75 40.85,42.57 38.25,42.57 38.16,42.66 38.16,43.24 38.32,43.41 38.88,43.41 39.12,43.65 39.12,44.3 39.48,44.66 40.45,44.66
5V_VIN on BOTTOM (solid shape): 42.66,50.51 42.66,50.19 42.97,49.87 44.56,49.87 44.63,49.81 44.63,49.3 45.36,48.56 45.36,47.57 43.3,47.57 42.66,48.22 39.53,48.22 39.19,47.88 38.51,47.88 38.39,48.01 38.39,48.9 38.72,49.24 38.77,49.24 40.17,50.63 42.53,50.63
+0.675VS on TOP (solid shape): 156.27,41.36 156.27,40.27 155.23,39.23 154.7,39.23 154.7,39.23 150.71,39.23 150.53,39.4 150.53,40.47 151.11,41.06 154.31,41.06 154.85,41.59 156.04,41.59
+0.675VS on BOTTOM (solid shape): 152.27,40.9 152.27,39.31 152.08,39.12 150.69,39.12 150.43,39.38 150.43,40.94 150.56,41.07 152.1,41.07
+0.675VS on IN2 (solid shape): outline of 166 points within 129.62,38.72 152.79,46.26
+0.675VSP on BOTTOM (solid shape): 151.13,38.87 151.13,38.36 151.64,38.36 151.64,38.93 151.96,38.93 152.15,38.74 152.15,34.36 152.47,34.04 152.47,32.46 152.57,32.35 152.57,32.21 152.5,32.15 151.72,32.15 151.67,32.2 151.67,32.3 150.31,33.66 150.31,38.81 150.43,38.93 151.07,38.93
+1.05VALW on TOP (solid shape): 160.95,55.19 164.18,55.19 164.23,55.14 165.27,55.14 165.56,54.85 165.56,50.28 165,49.71 163.66,49.71 162.79,48.85 159.92,48.85 159.27,49.51 159.27,52.97 157.08,55.15 157.08,56.02 157.2,56.13 157.23,56.12 157.44,56.12 157.64,56.22 159.93,56.22
+1.05VALW on TOP (solid shape): 99.03,96.58 99.06,96.5 99.02,96.43 98.84,95.87 99.3,95.51 99.33,95.5 99.35,95.46 99.35,94.62 99.54,94.43 99.54,93.77 99.58,93.73 99.58,93.72 100.11,93.19 100.11,89.18 99.24,88.31 99.24,87.54 99.11,87.41 98.56,87.41 98.05,87.93 98.04,87.94 97.97,88.07 97.88,88.18 97.82,88.24 97.82,91.07 97.83,91.11 97.87,91.12 98.19,91.48 97.87,91.83 97.83,91.85 97.82,91.88 97.82,96 97.83,96.09 97.82,96.19 97.82,96.4 98.08,96.65 98.96,96.65
+1.05VALW on TOP (solid shape): 144.55,92.99 145.23,92.99 146.07,92.15 147.8,92.15 148.53,91.41 148.52,91.4 148.52,90.23 149.14,89.61 149.16,89.59 149.51,89.24 150.21,89.24 150.21,89.24 151.58,89.24 151.6,89.23 151.96,89.23 153.35,87.84 153.48,87.77 153.63,87.76 153.65,87.77 153.92,87.5 154.17,87.5 154.19,87.49 163.16,87.49 166.02,84.62 166.02,83.84 165.43,83.24 164.26,83.24 162.72,84.78 155.55,84.78 155.42,84.91 152.19,84.91 151.97,85.13 151.5,85.13 151.3,85.2 151.09,85.14 151.08,85.13 150.96,85.13 150.67,85.29 150.37,85.13 149.35,85.13 149.27,85.17 149.25,85.26 148.91,85.71 148.56,85.26 148.55,85.17 148.47,85.13 147.33,85.13 142.71,89.75 142.71,90.24 142.75,90.28 142.75,92.2 141.74,93.2 141.74,93.21 141.1,94 140.31,94.64 140.3,94.64 139.27,95.68 136.63,95.68 135.95,96.35 135.95,98.52 136.61,99.17 138.36,99.17
+1.05VALW on TOP (solid shape): outline of 169 points within 56.14,67.44 61.34,77.99
+1.05VALW on BOTTOM (solid shape): 100.06,94.62 100.06,92.79 99.51,92.24 98.33,92.24 98.08,92.49 98.08,92.71 98.41,93.04 98.41,93.13 98.48,93.2 98.48,94.88 98.59,94.98 99.7,94.98
+1.05VALW on IN1 (solid shape): outline of 5139 points within 56.11,51.01 173.58,99.66
+1.05VALWP on TOP (solid shape): 66.77,67.55 66.77,65.88 66.5,65.62 61.98,65.62 61.07,64.71 56.36,64.71 55.96,65.11 55.96,65.62 56.17,65.82 56.62,65.82 56.83,66.02 56.83,66.38 57.64,67.19 60.71,67.19 60.98,67.46 60.98,67.96 61.25,68.22 66.09,68.22
+1.05VS on TOP (solid shape): 106.08,75.82 106.08,75.24 106.25,75.06 106.31,75.06 106.33,75.04 107.52,75.04 107.68,74.88 107.68,73.28 107.42,73.03 107.07,73.03 107.05,73.04 106.55,73.04 105.37,74.22 104.76,74.22 104.7,74.27 104.7,74.81 105.24,75.34 105.24,75.77 105.34,75.87 106.03,75.87
+1.05VS on TOP (solid shape): 110.85,81.6 110.85,81.48 110.85,81.48 110.85,80.79 110.95,80.7 111,80.62 111.07,80.57 111.14,80.5 111.46,80.5 111.56,80.4 111.56,79.94 111.46,79.84 111.06,79.84 110.85,80.04 110.85,80.35 110.85,80.36 110.83,80.39 110.83,80.45 110.77,80.45 110.69,80.52 110.68,80.52 110.62,80.58 110.24,80.58 110.19,80.63 110.19,81.42 110.22,81.45 110.22,81.82 110.29,81.9 110.55,81.9
+1.05VS on TOP (solid shape): 155.77,55.53 155.84,55.53 157.84,53.53 157.84,52.97 157.84,52.97 157.84,50.42 157.71,50.3 148.12,50.3 147.91,50.5 147.91,50.53 147.71,50.73 147.71,53.53 148.14,53.96 153.73,53.96 154.21,53.47 155.38,53.47 155.61,53.7 155.61,54.24 155.18,54.66 155.18,54.68 155.07,54.9 154.85,55.01 154.83,55.01 154.72,55.13 154.72,55.51 154.85,55.63 155.67,55.63
+1.05VS on TOP (solid shape): 113.14,82.53 113.14,82.09 113.44,81.79 113.98,81.79 114.07,81.7 114.07,80.89 114.33,80.62 114.33,79.91 114.73,79.52 114.74,79.53 115.37,79.53 115.88,80.04 116.62,80.04 117,79.66 117,79.3 116.82,79.13 115.83,79.13 115.73,79.03 115.73,77.32 116.21,76.84 116.21,76.43 115.89,76.12 115.31,76.12 115.31,76.1 114.75,76.1 114.75,76.12 114.72,76.12 114.7,76.13 114.29,76.13 114.2,76.22 114.2,76.41 114.33,76.54 114.33,76.58 114.48,76.73 114.48,76.8 114.66,77.15 114.38,77.42 114.33,77.43 114.33,77.49 114.15,77.67 114.15,78.63 114.1,78.69 114.1,78.85 113.83,79.12 113.83,79.54 113.42,79.63 113.39,79.61 113.14,79.86 113.14,80.16 113.11,80.2 113.1,80.21 112.92,80.42 112.64,80.42 112.63,80.41 112.29,80.41 111.67,81.03 111.67,82.6 111.7,82.63 113.04,82.63
+1.05VS on TOP (solid shape): outline of 461 points within 99.6,82.25 103.85,95.51
+1.05VS on BOTTOM (solid shape): 107.87,73.02 107.87,72.84 107.76,72.74 106.83,72.74 106.74,72.83 106.74,73.72 106.85,73.83 107.06,73.83
+1.05VS on BOTTOM (solid shape): 126.58,61.63 126.58,60.46 126.32,60.21 123.12,60.21 122.99,60.33 122.99,61.43 123.45,61.88 126.32,61.88
+1.05VS on BOTTOM (solid shape): 101.85,93 101.85,91.85 101.31,91.31 101.31,90.15 101.12,89.96 100.94,89.96 99.85,91.05 97.5,91.05 97.35,91.2 97.35,91.6 97.39,91.61 97.57,91.72 97.67,91.91 97.68,91.95 100.41,91.95 101.02,92.56 101.02,93.05 101.2,93.23 101.61,93.23
+1.05VS on BOTTOM (solid shape): 106.76,74.91 106.76,74.7 106.73,74.64 106.66,74.58 105.9,73.82 105.9,73.81 105.88,73.78 105.75,73.64 105.62,73.64 105.47,73.49 105.27,73.49 105.16,73.59 105.16,73.94 105.16,74.58 105.57,74.99 105.57,75.04 105.61,75.08 105.61,75.08 105.95,75.42 106.26,75.42
+1.05VS on BOTTOM (solid shape): 111.18,75.07 111.24,75.06 111.28,75.06 111.32,75.04 111.45,74.91 111.45,74.74 110.98,74.26 110.98,73.73 110.99,73.71 110.99,73.66 110.99,73.62 110.88,73.51 110.73,73.51 109.89,74.35 109.89,74.46 110,74.58 110.03,74.58 110.07,74.62 110.13,74.62 110.14,74.6 110.19,74.55 110.24,74.51 110.32,74.43 110.57,74.43 110.95,74.8 110.95,74.88 111.16,75.09
+1.05VS on BOTTOM (solid shape): 110.21,73.74 110.21,72.9 110.21,72.88 110.07,72.73 109.96,72.76 109.89,72.84 109.88,72.87 109.82,72.93 109.66,72.93 109.31,73.28 109.31,73.35 109.08,73.58 109.08,73.62 109.09,73.67 109.16,73.79 109.31,73.82 109.39,73.79 109.51,73.91 110.05,73.91
+1.05VS on BOTTOM (solid shape): 113.15,82.94 113.2,82.94 113.26,82.93 113.37,82.8 113.33,82.64 113.31,82.61 113.31,82.14 113.35,82.08 113.35,81.93 113.02,81.6 112.8,81.38 112.8,81.11 112.99,80.92 113.3,80.92 113.34,80.96 113.82,81.44 113.82,81.87 113.82,82.12 113.95,82.25 114.07,82.25 114.2,82.12 114.2,81.26 114.16,81.22 114,81.06 114,80.98 113.99,80.97 113.97,80.86 114,80.7 114.01,80.69 114.02,80.67 114.06,80.62 114.18,80.5 114.18,80.37 114,80.19 113.7,80.19 113.57,80.32 113.18,80.32 113.15,80.36 113.01,80.36 112.78,80.45 112.56,80.36 112.28,80.36 112.21,80.43 112.17,80.43 111.82,80.78 111.82,81.01 111.95,81.14 111.95,81.37 111.41,81.9 111.41,82.07 111.59,82.25 111.66,82.25 111.73,82.33 112.3,82.33 112.47,82.5 112.48,82.5 112.58,82.57 112.65,82.67 112.65,82.68 112.88,82.91 112.93,82.91 112.96,82.94 113.13,82.94
+1.05VS on IN2 (solid shape): outline of 4941 points within 103.28,50.45 153.91,84.08
+1.05VS_R on TOP (solid shape): 155.28,49.79 155.28,49.29 154.99,49 153.83,49 152.66,47.83 152,47.83 151.72,48.11 151.72,49.18 152.53,49.99 155.07,49.99
+1.05VS_SOC on TOP (solid shape): 108.53,75.68 108.53,75.32 108.35,75.14 106.37,75.14 106.33,75.18 106.33,75.76 106.42,75.85 108.36,75.85
+1.8VALW on TOP (solid shape): 51.62,70.62 51.62,68.18 51.57,68.13 50.86,68.13 50.81,68.18 50.81,68.59 49.99,69.4 48.95,69.4 48.77,69.58 48.77,70.24 49.46,70.93 51.32,70.93
+1.8VALW on TOP (solid shape): 86.94,82.54 86.84,82.24 87.06,82.07 87.1,82.07 87.1,81.57 86.88,81.34 85.91,81.34 85.63,81.62 85.63,82.69 85.89,82.94 86.55,82.94
+1.8VALW on TOP (solid shape): 74.02,75.03 74.02,71.44 73.58,71 71.74,71 71.21,71.53 71.21,71.95 71.27,72.01 71.72,72.01 71.78,72.07 71.78,72.52 71.72,72.58 71.27,72.58 71.21,72.65 71.21,72.77 71.27,72.84 71.72,72.84 71.78,72.9 71.78,73.34 71.72,73.41 71.27,73.41 71.21,73.47 71.21,74.56 71.88,75.24 73.81,75.24
+1.8VALW on TOP (solid shape): 96.53,83.69 96.53,82.48 96.39,82.34 96.39,81.88 96.65,81.62 96.65,81.6 96.84,81.36 97.13,81.37 97.15,81.37 97.29,81.37 97.34,81.41 97.95,81.41 97.95,81.27 98.71,81.27 98.71,81.41 98.86,81.41 98.89,81.4 98.91,81.36 99.27,81 99.62,81.36 99.62,81.41 100.09,81.41 100.24,81.27 100.24,80.8 100.04,80.6 100.01,80.61 99.77,80.62 99.58,80.49 96.75,80.49 96.74,80.5 95.87,80.5 94.85,81.52 94.85,83.19 95.43,83.77 96.44,83.77
+1.8VALW on TOP (solid shape): outline of 129 points within 84.74,74.43 100.11,80.38
+1.8VALW on BOTTOM (solid shape): 105.49,79.08 105.52,79.05 106.28,78.29 106.28,78.11 106.17,78 104.74,78 104.64,78.1 104.44,78.29 104.44,78.53 104.54,78.63 104.55,78.63 105.09,79.17 105.4,79.17
+1.8VALW on VCC: 68.35,75.94 68.35,77.99 77.73,87.38 89.54,87.38 90.81,88.65 96.15,88.65 97.04,89.54 105.34,89.54 108,86.87 108.11,86.87 108.11,79.43 107.04,78.36 106.15,78.36 105.9,78.11 104.63,78.11 104.37,77.86 104.23,77.86 104.23,77.86 104.12,77.86 104.12,77.86 100.8,77.86 99.65,79 96.22,79 95.59,79.63 93.07,79.63 92.18,78.75 90.13,78.75 89.62,79.25 88.53,79.25 88.4,79.38 79.16,79.38 73.04,73.26 71.03,73.26
+1.8VALW on IN2: 56.97,73.07 58.33,74.43 65.82,74.43 67.6,76.21 73.49,76.21 73.95,75.75 73.95,74.56 73.94,74.55 73.94,74.29 71.39,71.74 67.21,71.74 65.97,70.49 56.17,70.49 54.77,69.1 50.96,69.1 50.45,69.6 50.45,71.38 51.85,72.78 56.39,72.78 56.77,72.74 56.97,73.05
+1.8VALWP on TOP (solid shape): 71.02,74.3 71.02,73.28 71.08,73.22 71.53,73.22 71.59,73.15 71.59,73.03 71.53,72.96 71.08,72.96 71.02,72.9 71.02,72.52 71.08,72.46 71.53,72.46 71.59,72.39 71.59,72.27 71.53,72.2 71.08,72.2 71.02,72.14 71.02,71.75 71.02,71.74 70.96,71.69 69.85,71.69 69.15,71 68.8,71 68.73,71.06 68.73,72.39 68.35,72.77 67.53,72.77 67.33,72.96 67.33,74.49 67.53,74.68 70.64,74.68
+1.8VS on TOP (solid shape): 18.81,96.26 19.1,96.26 19.46,95.89 19.46,94.75 19.34,94.62 18.19,94.62 17.86,94.95 17.86,96.17 17.96,96.27 18.8,96.27
+1.8VS on TOP (solid shape): 33.62,23.03 33.62,21.36 33.41,21.14 32.6,21.14 32.51,21.23 32.51,21.41 32.61,21.41 32.61,22.3 32.48,22.3 32.48,23.03 32.7,23.25 33.41,23.25
+1.8VS on TOP (solid shape): 55.43,77.05 55.43,75.25 55.1,74.91 55.1,71.5 54.76,71.16 54.07,71.16 54.01,71.1 54.01,71.04 54.01,71.03 54.01,70.75 53.98,70.72 53.7,70.72 53.68,70.74 53.68,71.26 52.33,71.26 52.33,70.76 52.3,70.72 51.88,70.72 51.8,70.81 51.8,73.8 52.38,74.38 52.38,76.61 52.92,77.15 55.33,77.15
+1.8VS on TOP (solid shape): 114.59,74.88 114.59,74.81 114.97,74.42 114.98,74.41 115.04,74.33 115.12,74.27 115.12,74.27 115.35,74.05 115.35,72.7 114.76,72.12 114.76,71.66 114.66,71.56 114.41,71.56 114.23,71.74 114.23,72.62 114.41,72.8 114.41,73.54 114.03,73.92 114.03,74.88 114.13,74.99 114.48,74.99
+1.8VS on TOP (solid shape): 126,98.86 129.7,98.86 132.41,96.16 132.41,92.86 131.36,91.81 131.36,89.68 131.35,89.67 131.35,88.12 133.33,86.14 134.58,86.14 135.82,84.89 135.82,84.13 135.77,84.08 135.01,84.08 134.14,84.95 132.7,84.95 132.11,84.36 131.33,84.36 129.05,86.63 129.05,89.85 128.63,90.27 128.63,93.33 127.92,94.04 127.92,94.9 127.8,95.02 127.8,96.76 127.42,97.13 126.45,97.13 126.35,97.04 126.34,97.04 126.1,96.76 126.2,96.41 126.35,96.27 126.35,95.79 126.22,95.66 125.56,95.66 125.23,95.99 123.22,95.99 123.04,96.17 123.04,97.23 123.21,97.53 123.04,97.83 123.04,98.35 121.1,100.3 121.1,100.99 121.26,101.16 123.7,101.16
+1.8VS on TOP (solid shape): outline of 536 points within 20.86,31 32.75,93.68
+1.8VS on BOTTOM (solid shape): 130,89.79 130,87.81 129.5,87.3 129.11,87.3 128.3,86.49 127.89,86.49 127.54,86.49 127.29,86.75 127.29,87.74 127.54,87.99 127.56,87.99 127.87,88.13 127.92,88.47 127.92,88.48 127.92,89.67 128.17,89.92 129.88,89.92
+1.8VS on BOTTOM (solid shape): 113.28,76.08 113.41,75.95 113.45,75.95 113.5,75.94 113.56,75.93 114,75.49 114.07,75.49 114.58,74.99 114.58,74.77 114.42,74.61 114.17,74.61 114.07,74.7 113.91,74.7 113.87,74.67 113.85,74.66 113.83,74.66 113.72,74.55 113.49,74.55 112.96,75.09 112.96,75.24 113.22,75.5 113.22,75.67 113.21,75.68 113.21,75.72 113.13,75.8 113.08,75.83 113.05,75.88 113.03,75.9 113.03,75.98 113.13,76.08
+1.8VS on IN1 (solid shape): 124.1,100.93 124.1,100.06 123.85,99.81 120.76,99.81 120.53,100.04 120.53,100.79 120.89,101.14 123.89,101.14
+1.8VS on IN1 (solid shape): 55.36,81.89 55.36,80.3 55.25,80.19 55.25,79.05 55.37,78.93 55.37,77.48 55.65,77.2 55.65,75.64 55.51,75.5 54.16,75.5 54.03,75.62 54.03,77.4 54.05,77.42 54.05,77.58 54.21,77.88 54.05,78.18 54.05,82.2 54.32,82.47 54.78,82.47
+1.8VS on IN1 (solid shape): outline of 109 points within 17.66,89.92 24.04,96.45
+1.8VS on IN1 (solid shape): outline of 363 points within 23.27,22.51 34.58,34.55
+1.8VS_OUT on TOP (solid shape): 52.74,70.59 53.24,70.59 53.24,70.6 53.54,70.6 53.54,70.59 54.12,70.59 54.12,70.6 55.76,70.6 56.01,70.34 56.01,69.66 55.78,69.43 55.78,68.79 55.66,68.67 54.21,68.67 53.96,68.41 53.89,68.41 53.65,68.18 52.89,68.18 52.79,68.28 52.79,68.84 52.56,69.07 52.18,69.07 51.9,69.35 51.9,70.52 51.97,70.59 52.44,70.59 52.44,70.6 52.74,70.6
+1.35V on TOP (solid shape): 51.57,66.73 51.57,66.15 52.05,65.67 52.08,65.67 52.31,65.44 52.31,63.48 51.95,63.13 51.47,63.13 50.93,63.66 50.93,65.24 50.33,65.85 50.33,66.24 50.78,66.69 50.78,66.71 50.85,66.78 51.52,66.78
+1.35V on TOP (solid shape): outline of 5744 points within 88.17,27.06 140.42,54.36
+1.35V on BOTTOM (solid shape): 140.4,40.01 140.4,39.25 139.83,39.25 139.83,37.22 140.4,37.22 140.4,33.98 139.83,33.98 139.83,31.95 140.4,31.95 140.4,31.39 140.25,31.24 137.68,31.24 137.66,31.26 136.6,31.26 133.94,33.92 91.88,33.92 91.32,34.48 91.32,36.38 91.75,36.81 91.92,36.81 91.93,36.81 92.05,36.79 92.18,36.81 92.19,36.81 94.72,36.81 94.79,36.78 94.82,36.71 95.17,36.36 95.53,36.71 95.56,36.78 95.63,36.81 97.11,36.81 97.39,36.68 97.67,36.81 98.98,36.81 99.21,36.73 99.43,36.81 102.16,36.81 102.17,36.77 102.52,36.45 102.88,36.77 102.88,36.81 108.77,36.81 109,36.73 109.22,36.81 127.91,36.81 127.92,36.78 128.25,36.56 128.58,36.78 128.6,36.81 129.07,36.81 129.08,36.78 129.42,36.51 129.77,36.78 129.78,36.81 131.81,36.81 135.09,40.1 137.69,40.1 137.73,40.14 140.27,40.14
+1.35V_SOC on TOP (solid shape): outline of 5139 points within 90.37,54.87 123.94,72.21
+1.35V_SOC on BOTTOM (solid shape): 103.53,70.58 103.53,70.36 103.52,70.27 103.52,70.19 103.49,70.03 103.53,69.87 103.53,69.86 103.53,69.81 103.52,69.78 103.35,69.61 103.1,69.61 103.05,69.69 102.98,69.74 102.89,69.8 102.8,69.82 102.78,69.83 102.58,70.03 102.58,70.28 102.74,70.44 102.76,70.44 102.92,70.52 102.99,70.67 102.99,70.69 103.03,70.73 103.39,70.73
+1.35V_SOC on BOTTOM (solid shape): 107.43,72.06 107.43,72.02 107.63,71.82 107.67,71.82 107.73,71.76 107.86,71.76 107.98,71.64 107.98,71.38 107.96,71.34 107.95,71.3 107.85,71.2 107.83,71.21 107.73,71.22 107.63,71.21 107.62,71.21 107.55,71.21 107.46,71.29 107.46,71.31 107.39,71.43 107.27,71.5 107.25,71.51 107.07,71.69 106.9,71.69 106.89,71.69 106.75,71.74 106.6,71.71 106.57,71.7 106.36,71.92 106.24,71.92 106.23,71.92 106.09,71.92 106.07,71.94 106.04,71.94 105.95,72.03 105.95,72.22 106.17,72.43 106.17,72.44 106.26,72.53 106.97,72.53
+1.35VP on BOTTOM (solid shape): 150.12,40.25 150.12,33.66 151.49,32.29 151.49,32.22 151.49,32.19 151.54,32.14 151.54,32.04 151.64,31.95 152.5,31.95 152.55,31.9 152.55,31.8 152.5,31.74 151.72,31.74 151.67,31.69 150.62,31.69 150.61,31.71 150.56,31.71 148.77,33.5 143.82,33.5 141.66,31.34 140.62,31.34 140.57,31.39 140.57,39.95 140.96,40.34 150.02,40.34
+1.35VS on TOP (solid shape): 53.23,63.54 53.73,63.54 53.73,63.56 54.03,63.56 54.03,63.54 54.53,63.54 54.53,63.56 55.02,63.56 55.17,63.4 55.17,62.51 54.95,62.29 53.35,62.29 52.79,62.84 52.79,63.48 52.86,63.56 53.23,63.56
+1.35VS on TOP (solid shape): 110.2,75.95 110.42,75.95 110.69,75.68 110.69,74.69 110.56,74.57 110.41,74.57 110.35,74.51 110.35,74.03 109.99,73.67 109.59,73.67 109.59,73.66 109.5,73.66 108.9,73.06 108.68,73.06 108.59,73.14 108.59,74.32 108.64,74.37 109.38,74.37 109.5,74.5 109.64,74.49 109.75,74.51 109.97,74.8 109.79,75.12 109.76,75.13 109.76,75.93 109.81,75.98 110.17,75.98
+1.35VS on TOP (solid shape): outline of 189 points within 104.14,81.41 121.6,100.57
+1.35VS on BOTTOM (solid shape): 121.88,95.94 122.21,95.61 122.21,94.42 122.05,94.27 119.62,94.27 119.49,94.4 119.49,95 119.84,95.36 119.83,95.37 119.88,95.42 119.88,95.78 120.05,95.94 121.85,95.94
+1.35VS on BOTTOM (solid shape): 111.8,81.3 111.8,81.19 111.66,81.05 111.52,81.05 111.35,81.21 111.21,81.21 111.18,81.19 111.17,81.18 111,81.09 110.91,80.93 110.91,80.91 110.8,80.8 110.11,80.8 109.44,81.47 109.44,81.58 109.44,81.58 109.5,81.76 109.67,81.84 109.7,81.85 109.74,81.86 109.77,81.86 110.15,81.48 110.15,81.48 110.21,81.39 110.29,81.34 110.33,81.3 110.45,81.3 110.55,81.3 110.57,81.32 110.68,81.39 110.75,81.51 110.76,81.51 110.8,81.55 110.8,81.77 110.64,81.93 110.64,82.08 110.74,82.18 110.92,82.18
+1.35VS on IN1 (solid shape): 55.13,63.99 55.13,62.67 54.83,62.38 54.1,62.38 53.91,62.57 53.91,64.02 54.08,64.19 54.92,64.19
+1.35VS on IN1 (solid shape): outline of 2152 points within 85.78,72.51 109.89,91.16
+1.35VS_OUT on TOP (solid shape): 53.93,66.63 55.61,66.63 55.71,66.53 55.71,64.98 55.3,64.58 55.3,64.24 52.89,64.24 52.84,64.29 52.84,66.73 52.9,66.79 53.77,66.79
+3V_HDD on TOP (solid shape): 212.4,46.94 212.4,42.12 211.82,41.54 210.33,41.54 210.33,41.56 208.93,41.56 208.93,41.54 208.82,41.54 208.41,41.95 208.41,46.79 208.74,47.12 212.22,47.12
+3V_LAN on TOP (solid shape): 34.98,72.59 35.08,72.44 35.24,72.35 35.26,72.35 35.33,72.28 35.32,72.26 35.49,71.88 35.9,71.91 36.19,71.91 36.41,71.83 36.63,71.9 36.64,71.91 36.71,71.91 36.9,72.11 37.71,72.11 37.8,72.02 37.83,71.58 38.26,71.5 38.3,71.52 39.05,70.77 39.05,69.55 39.3,69.3 39.3,66.84 39.25,66.75 39.14,66.75 38.91,66.81 38.63,66.68 38.56,66.69 38.04,66.55 38.27,66.05 38.32,66.01 38.34,65.95 38.73,65.56 39.04,66.01 39.04,66.08 39.09,66.13 39.14,66.16 39.25,66.16 39.3,66.07 39.3,62.59 39.01,62.3 38.04,62.3 37.75,62.59 37.75,63.38 37.37,63.76 32.7,63.76 32.09,64.37 32.09,65.26 32.29,65.46 34.81,65.46 35.07,65.36 35.33,65.46 36.18,65.46 36.51,65.79 36.51,67.02 37,67.51 37,68.02 37.49,68.5 37.49,70.37 37.19,70.67 36.13,70.67 36.07,70.72 33.92,70.72 33.56,71.08 33.56,72.32 33.87,72.63 34.96,72.63
+3V_LAN on BOTTOM (solid shape): 33.94,72.81 33.94,72.81 34.79,71.95 34.79,71.85 35.03,71.61 35.03,71.51 34.89,71.37 34.72,71.37 34.69,71.38 34.58,71.48 33.05,71.48 33.03,71.46 32.85,71.64 32.85,71.69 32.85,71.87 32.82,71.9 32.82,72.91 32.88,72.96 33.79,72.96
+3V_LAN on BOTTOM (solid shape): 39.25,67.83 39.25,67.12 39.1,66.96 38.49,66.96 38.29,67.17 38.29,67.35 38.29,67.52 38.16,67.65 37.24,67.65 37.19,67.7 37.19,67.8 37.29,67.9 38.31,67.9 38.33,67.92 38.56,67.92 38.63,68 39.08,68
+3V_LAN on BOTTOM (solid shape): 34.4,67.14 34.4,66.34 34.12,66.06 34.12,66.02 34.02,65.92 34.02,64.86 33.82,64.65 33.82,64.02 33.64,63.84 30.11,63.84 30.08,63.86 30.08,64.4 30.23,64.55 31.49,64.55 32.39,65.45 32.55,65.45 33.23,66.14 33.23,66.73 33.62,67.12 33.98,67.12 34.05,67.13 34.11,67.16 34.12,67.17 34.37,67.17
+3VALW on TOP (solid shape): 74,79.13 74,77.81 73.99,77.81 73.99,75.68 73.73,75.41 71.87,75.41 71.78,75.5 71.78,77.98 71.79,77.99 71.79,79.03 72.11,79.35 73.78,79.35
+3VALW on TOP (solid shape): 190.36,24.32 190.5,24.32 190.56,24.26 190.56,24.11 190.73,23.93 192.13,23.93 192.21,23.86 192.21,21.52 191.98,21.29 189.31,21.29 189.11,21.5 189.11,24.62 189.19,24.69 189.99,24.69
+3VALW on TOP (solid shape): 59.57,58.6 59.57,58.04 59.9,57.71 60.45,57.71 61.7,56.47 62.28,56.47 62.29,56.48 62.29,57.01 62.3,57.02 62.53,57.02 62.54,57.02 62.54,56.48 62.55,56.47 63.09,56.47 63.1,56.48 63.1,57.02 63.11,57.02 63.33,57.02 63.33,57.02 63.33,56.5 63.37,56.46 65.04,56.46 65.11,56.4 65.11,53.86 65.03,53.78 60.45,53.78 56.5,57.74 56.5,58.43 56.88,58.81 59.36,58.81
+3VALW on TOP (solid shape): 31.33,94.23 31.33,93.41 31.83,92.91 33.25,92.91 34.24,91.91 34.25,91.89 34.27,91.69 34.34,91.5 34.34,90.06 34.03,89.76 34.01,89.77 33.54,89.65 33.29,89.23 33.29,89.22 33.15,89.09 33.15,88.3 32.85,87.99 31.38,87.99 31.1,88.27 31.1,89.95 31.53,90.38 31.53,92.06 31.34,92.25 30.98,92.25 30.47,92.76 30.47,94.04 30.79,94.36 31.2,94.36
+3VALW on BOTTOM (solid shape): 200.36,89.54 200.36,88.15 200.06,87.84 198.51,87.84 198.41,87.94 198.41,88.58 198.56,88.73 199.3,88.73 199.42,88.86 199.42,89.65 199.47,89.7 200.21,89.7
+3VALW on BOTTOM (solid shape): 207.47,40.55 207.47,35.2 207.2,34.92 204.87,34.92 204.51,35.28 204.51,36.95 205.08,36.95 205.08,38.98 204.51,38.98 204.51,40.47 204.83,40.79 207.23,40.79
+3VALW on BOTTOM (solid shape): 206.15,20.96 206.15,11.31 202.76,7.92 202.77,7.9 202.77,5.42 202.52,5.16 199.19,5.16 199.02,5.34 199.02,7.6 199.42,8.01 199.42,9.69 201.89,12.15 201.89,17.74 198.41,21.22 189.39,21.22 189.26,21.34 189.26,23.58 193.17,23.58 193.17,23.53 193.18,23.48 193.19,23.43 193.22,23.38 193.25,23.33 193.28,23.29 193.32,23.26 193.37,23.23 193.42,23.21 193.47,23.2 193.52,23.2 193.58,23.2 193.63,23.21 193.68,23.23 193.72,23.26 193.77,23.29 193.8,23.33 193.83,23.38 193.86,23.43 193.87,23.48 193.88,23.53 193.88,23.58 193.87,23.64 193.86,23.69 193.83,23.73 193.8,23.78 193.77,23.82 193.72,23.85 193.68,23.88 193.63,23.9 193.58,23.91 193.52,23.91 193.47,23.91 193.42,23.9 193.37,23.88 193.32,23.85 193.28,23.82 193.25,23.78 193.22,23.73 193.19,23.69 193.18,23.64 193.17,23.58 189.26,23.58 189.26,23.88 189.52,24.14 202.98,24.14
+3VALW on BOTTOM (solid shape): outline of 212 points within 29.83,54.82 59.34,63.48
+3VALW on IN1 (solid shape): 34.63,89.9 34.63,88.15 34.27,87.79 31.88,87.79 31.61,88.07 31.61,89.87 32.06,90.33 34.2,90.33
+3VALW on IN1 (solid shape): 201.02,88.4 201.02,87.08 200.69,86.75 199.04,86.75 198.31,87.49 198.31,88.48 198.66,88.83 200.59,88.83
+3VALW on IN1: outline of 242 points within 47.63,13.25 210.4,82.12
